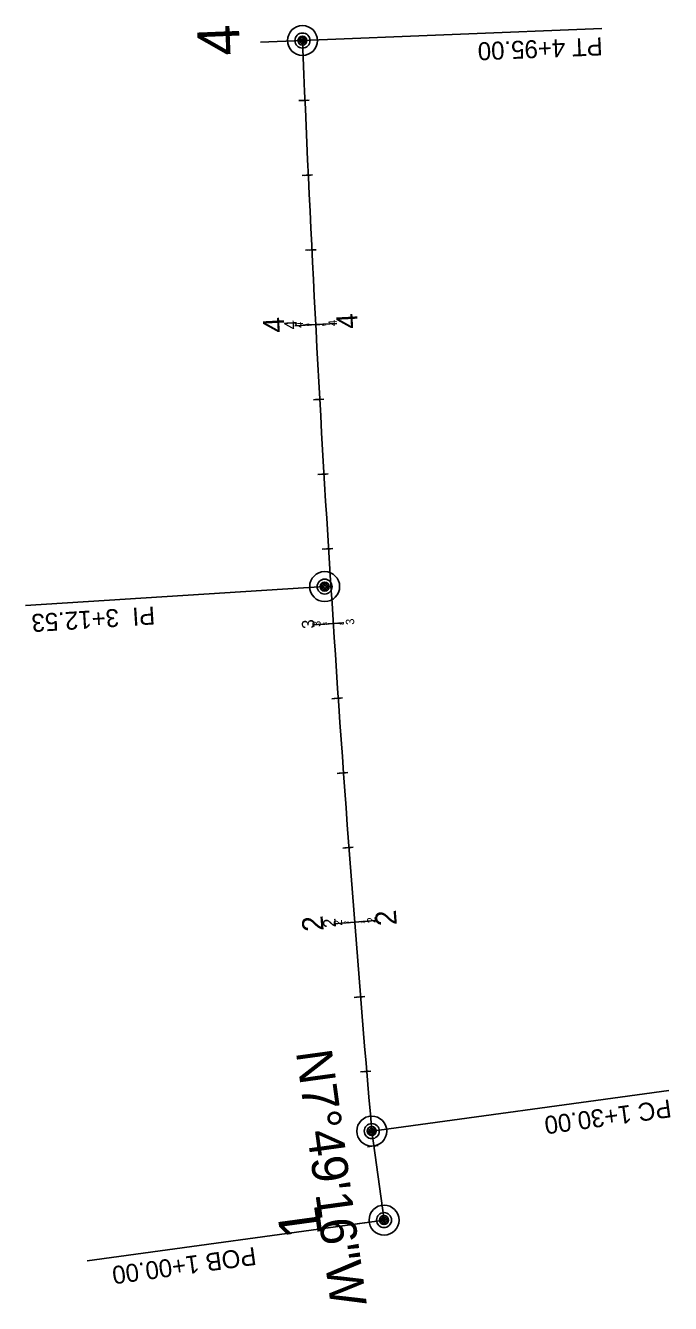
# Model space of a CAD drawing. Extents: x 594355 to 602437, y 155170 to 155921.
# Drawn here: x 594355.1 to 594570.2, y 155170.4 to 155597.2 of the extents above; entities that cross this region are included whole.
import ezdxf

# ---------------------------------------------------------------- set-up
doc = ezdxf.new("R2010")
doc.units = 0
for name, color, linetype in [('P_ALI_10', 7, 'Continuous'), ('P_ALI_100', 7, 'Continuous'), ('P_ALI_100_Equation', 7, 'Continuous'), ('P_ALI_100_Sta', 7, 'Continuous'), ('P_ALI_100_Tic', 7, 'Continuous'), ('P_ALI_100_TPI', 7, 'Continuous'), ('P_ALI_10_Flipped', 7, 'Continuous'), ('P_ALI_10_Sta', 7, 'Continuous'), ('P_ALI_10_Tic', 7, 'Continuous'), ('P_ALI_10_TPI', 7, 'Continuous'), ('P_ALI_20', 7, 'Continuous'), ('P_ALI_20_Flipped', 7, 'Continuous'), ('P_ALI_20_Sta', 7, 'Continuous'), ('P_ALI_20_Tic', 7, 'Continuous'), ('P_ALI_20_TPI', 7, 'Continuous'), ('P_ALI_30', 7, 'Continuous'), ('P_ALI_30_Sta', 7, 'Continuous'), ('P_ALI_30_Tic', 7, 'Continuous'), ('P_ALI_30_TPI', 7, 'Continuous'), ('P_ALI_50', 7, 'Continuous'), ('P_ALI_50_CPIData', 7, 'Continuous'), ('P_ALI_50_Flipped', 7, 'Continuous'), ('P_ALI_50_PIData', 7, 'Continuous'), ('P_ALI_50_Sta', 7, 'Continuous'), ('P_ALI_50_Tic', 7, 'Continuous'), ('P_ALI_50_TPI', 7, 'Continuous'), ('P_WAL', 7, 'Continuous')]:
    doc.layers.add(name, color=color, linetype=linetype)

msp = doc.modelspace()

# ---------------------------------------------------------------- linework, layer by layer
at = {"layer": 'P_ALI_10'}
msp.add_line((594474.66, 155198.21), (594470.58, 155227.93), dxfattribs=at)
msp.add_arc((602431.92, 155916.42), 7991.05, 182.325576, 184.942623, dxfattribs=at)
at = {"layer": 'P_ALI_100'}
msp.add_line((594474.66, 155198.21), (594470.58, 155227.93), dxfattribs=at)
msp.add_arc((602431.92, 155916.42), 7991.05, 182.325576, 184.942623, dxfattribs=at)
at = {"layer": 'P_ALI_100_Tic'}
for points in [[(594433.46, 155591.59), (594447.45, 155592.16)], [(594444.88, 155496.9), (594451.87, 155497.27)], [(594450.75, 155396.98), (594457.74, 155397.44)], [(594457.88, 155297.15), (594464.86, 155297.69)], [(594460.79, 155196.3), (594474.66, 155198.21)]]:
    msp.add_lwpolyline(points, dxfattribs=at)
at = {"layer": 'P_ALI_100_TPI'}
for centre in [(594447.45, 155592.16), (594454.85, 155409.78), (594470.58, 155227.93), (594474.66, 155198.21)]:
    msp.add_circle(centre, 5, dxfattribs=at)
at = {"layer": 'P_ALI_10_Flipped'}
for points in [[(594448.98, 155572.21), (594448.28, 155572.18)], [(594450.1, 155547.24), (594449.4, 155547.2)], [(594451.29, 155522.27), (594450.59, 155522.23)], [(594453.26, 155497.34), (594451.87, 155497.27)], [(594453.92, 155472.34), (594453.22, 155472.3)], [(594455.34, 155447.38), (594454.65, 155447.34)], [(594456.85, 155422.43), (594456.15, 155422.39)], [(594459.13, 155397.53), (594457.74, 155397.44)], [(594460.1, 155372.54), (594459.4, 155372.49)], [(594461.84, 155347.6), (594461.14, 155347.55)], [(594463.66, 155322.67), (594462.96, 155322.62)], [(594466.25, 155297.8), (594464.86, 155297.69)], [(594467.53, 155272.83), (594466.83, 155272.77)], [(594469.58, 155247.91), (594468.88, 155247.86)], [(594471.95, 155223.07), (594471.26, 155222.97)]]:
    msp.add_lwpolyline(points, dxfattribs=at)
at = {"layer": 'P_ALI_10_Tic'}
for points in [[(594447.58, 155572.15), (594448.28, 155572.18)], [(594448.7, 155547.17), (594449.4, 155547.2)], [(594449.89, 155522.2), (594450.59, 155522.23)], [(594450.47, 155497.19), (594451.87, 155497.27)], [(594452.52, 155472.26), (594453.22, 155472.3)], [(594453.95, 155447.3), (594454.65, 155447.34)], [(594455.45, 155422.35), (594456.15, 155422.39)], [(594456.34, 155397.35), (594457.74, 155397.44)], [(594458.7, 155372.45), (594459.4, 155372.49)], [(594460.44, 155347.5), (594461.14, 155347.55)], [(594462.26, 155322.57), (594462.96, 155322.62)], [(594463.46, 155297.58), (594464.86, 155297.69)], [(594466.13, 155272.71), (594466.83, 155272.77)], [(594468.18, 155247.8), (594468.88, 155247.86)], [(594470.57, 155222.88), (594471.26, 155222.97)]]:
    msp.add_lwpolyline(points, dxfattribs=at)
at = {"layer": 'P_ALI_10_TPI'}
for centre in [(594447.45, 155592.16), (594454.85, 155409.78), (594470.58, 155227.93), (594474.66, 155198.21)]:
    msp.add_circle(centre, 0.5, dxfattribs=at)
at = {"layer": 'P_ALI_20'}
msp.add_line((594474.66, 155198.21), (594470.58, 155227.93), dxfattribs=at)
msp.add_arc((602431.92, 155916.42), 7991.05, 182.325576, 184.942623, dxfattribs=at)
at = {"layer": 'P_ALI_20_Flipped'}
for points in [[(594449.68, 155572.24), (594448.28, 155572.18)], [(594450.8, 155547.27), (594449.4, 155547.2)], [(594451.99, 155522.3), (594450.59, 155522.23)], [(594454.66, 155497.41), (594451.87, 155497.27)], [(594454.61, 155472.38), (594453.22, 155472.3)], [(594456.04, 155447.43), (594454.65, 155447.34)], [(594457.55, 155422.47), (594456.15, 155422.39)], [(594460.53, 155397.62), (594457.74, 155397.44)], [(594460.8, 155372.59), (594459.4, 155372.49)], [(594462.54, 155347.65), (594461.14, 155347.55)], [(594464.35, 155322.72), (594462.96, 155322.62)], [(594467.65, 155297.91), (594464.86, 155297.69)], [(594468.23, 155272.88), (594466.83, 155272.77)], [(594470.28, 155247.97), (594468.88, 155247.86)], [(594472.65, 155223.16), (594471.26, 155222.97)]]:
    msp.add_lwpolyline(points, dxfattribs=at)
at = {"layer": 'P_ALI_20_Tic'}
for points in [[(594446.89, 155572.12), (594448.28, 155572.18)], [(594448, 155547.14), (594449.4, 155547.2)], [(594449.2, 155522.16), (594450.59, 155522.23)], [(594449.07, 155497.12), (594451.87, 155497.27)], [(594451.82, 155472.22), (594453.22, 155472.3)], [(594453.25, 155447.26), (594454.65, 155447.34)], [(594454.75, 155422.3), (594456.15, 155422.39)], [(594454.94, 155397.26), (594457.74, 155397.44)], [(594458, 155372.4), (594459.4, 155372.49)], [(594459.74, 155347.45), (594461.14, 155347.55)], [(594461.56, 155322.52), (594462.96, 155322.62)], [(594462.06, 155297.48), (594464.86, 155297.69)], [(594465.43, 155272.66), (594466.83, 155272.77)], [(594467.49, 155247.74), (594468.88, 155247.86)], [(594469.87, 155222.78), (594471.26, 155222.97)]]:
    msp.add_lwpolyline(points, dxfattribs=at)
at = {"layer": 'P_ALI_20_TPI'}
for centre in [(594447.45, 155592.16), (594454.85, 155409.78), (594470.58, 155227.93), (594474.66, 155198.21)]:
    msp.add_circle(centre, 1, dxfattribs=at)
at = {"layer": 'P_ALI_30'}
msp.add_line((594474.66, 155198.21), (594470.58, 155227.93), dxfattribs=at)
msp.add_arc((602431.92, 155916.42), 7991.05, 182.325576, 184.942623, dxfattribs=at)
at = {"layer": 'P_ALI_30_Tic'}
for points in [[(594446.19, 155572.09), (594448.28, 155572.18)], [(594447.3, 155547.11), (594449.4, 155547.2)], [(594448.5, 155522.13), (594450.59, 155522.23)], [(594447.67, 155497.05), (594451.87, 155497.27)], [(594451.12, 155472.19), (594453.22, 155472.3)], [(594452.55, 155447.22), (594454.65, 155447.34)], [(594454.06, 155422.26), (594456.15, 155422.39)], [(594453.55, 155397.17), (594457.74, 155397.44)], [(594457.3, 155372.35), (594459.4, 155372.49)], [(594459.05, 155347.41), (594461.14, 155347.55)], [(594460.86, 155322.46), (594462.96, 155322.62)], [(594460.67, 155297.37), (594464.86, 155297.69)], [(594464.74, 155272.6), (594466.83, 155272.77)], [(594466.79, 155247.68), (594468.88, 155247.86)], [(594469.18, 155222.69), (594471.26, 155222.97)]]:
    msp.add_lwpolyline(points, dxfattribs=at)
at = {"layer": 'P_ALI_30_TPI'}
for centre in [(594447.45, 155592.16), (594454.85, 155409.78), (594470.58, 155227.93), (594474.66, 155198.21)]:
    msp.add_circle(centre, 1.5, dxfattribs=at)
at = {"layer": 'P_ALI_50'}
msp.add_line((594474.66, 155198.21), (594470.58, 155227.93), dxfattribs=at)
msp.add_arc((602431.92, 155916.42), 7991.05, 182.325576, 184.942623, dxfattribs=at)
at = {"layer": 'P_ALI_50_CPIData'}
msp.add_lwpolyline([(594454.85, 155409.78), (594355.06, 155403.44)], dxfattribs=at)
msp.add_lwpolyline([(594454.85, 155409.78), (594355.06, 155403.44)], dxfattribs=at)
at = {"layer": 'P_ALI_50_Flipped'}
for points in [[(594458.86, 155497.63), (594451.87, 155497.27)], [(594461.23, 155397.67), (594457.74, 155397.44)], [(594471.83, 155298.23), (594464.86, 155297.69)]]:
    msp.add_lwpolyline(points, dxfattribs=at)
at = {"layer": 'P_ALI_50_PIData'}
for points in [[(594447.45, 155592.16), (594547.36, 155596.22)], [(594447.45, 155592.16), (594547.36, 155596.22)], [(594470.58, 155227.93), (594569.65, 155241.54)], [(594470.58, 155227.93), (594569.65, 155241.54)], [(594474.66, 155198.21), (594375.59, 155184.6)], [(594474.66, 155198.21), (594375.59, 155184.6)]]:
    msp.add_lwpolyline(points, dxfattribs=at)
at = {"layer": 'P_ALI_50_Tic'}
for points in [[(594444.88, 155496.9), (594451.87, 155497.27)], [(594454.24, 155397.21), (594457.74, 155397.44)], [(594457.88, 155297.15), (594464.86, 155297.69)]]:
    msp.add_lwpolyline(points, dxfattribs=at)
at = {"layer": 'P_ALI_50_TPI'}
for centre in [(594447.45, 155592.16), (594454.85, 155409.78), (594470.58, 155227.93), (594474.66, 155198.21)]:
    msp.add_circle(centre, 2.5, dxfattribs=at)
at = {"layer": 'P_WAL'}
msp.add_line((594474.66, 155198.21), (594470.58, 155227.93), dxfattribs=at)
msp.add_arc((602431.92, 155916.42), 7991.05, 182.325576, 184.942623, dxfattribs=at)

# ---------------------------------------------------------------- texts
msp.add_text('00', height=0.14, rotation=3.7237).set_placement((594457.75, 155397.3))
at = {"layer": 'P_ALI_100_Equation'}
msp.add_text('N7%%d49\'16"W', height=12, rotation=277.8211, dxfattribs=at).set_placement((594445.24, 155254.42))
at = {"layer": 'P_ALI_100_Sta'}
for s, rotation, p in [('4', 92.3256, (594426.63, 155587.34)), ('1', 97.8211, (594454.16, 155193.16))]:
    msp.add_text(s, height=14, rotation=rotation, dxfattribs=at).set_placement(p)
at = {"layer": 'P_ALI_10_Flipped'}
for s, rotation, p in [('4', 273.0067, (594453.94, 155497.77)), ('3', 273.7237, (594459.81, 155397.97)), ('2', 274.4407, (594466.92, 155298.25))]:
    msp.add_text(s, height=1.4, rotation=rotation, dxfattribs=at).set_placement(p)
at = {"layer": 'P_ALI_10_Sta'}
for s, rotation, p in [('4', 93.0067, (594449.79, 155496.76)), ('3', 93.7237, (594455.67, 155396.91)), ('2', 94.4407, (594462.79, 155297.13))]:
    msp.add_text(s, height=1.4, rotation=rotation, dxfattribs=at).set_placement(p)
at = {"layer": 'P_ALI_20_Flipped'}
for s, rotation, p in [('4', 93.0067, (594458.9, 155496.84)), ('3', 93.7237, (594464.77, 155397.1)), ('2', 94.4407, (594471.9, 155297.44))]:
    msp.add_text(s, height=2.8, rotation=rotation, dxfattribs=at).set_placement(p)
at = {"layer": 'P_ALI_20_Sta'}
for s, rotation, p in [('4', 93.0067, (594447.71, 155496.25)), ('3', 93.7237, (594453.6, 155396.37)), ('2', 94.4407, (594460.73, 155296.58))]:
    msp.add_text(s, height=2.8, rotation=rotation, dxfattribs=at).set_placement(p)
at = {"layer": 'P_ALI_30_Sta'}
for s, rotation, p in [('4', 93.0067, (594445.64, 155495.75)), ('3', 93.7237, (594451.53, 155395.84)), ('2', 94.4407, (594458.67, 155296.02))]:
    msp.add_text(s, height=4.2, rotation=rotation, dxfattribs=at).set_placement(p)
at = {"layer": 'P_ALI_50_CPIData'}
msp.add_text('PI  3+12.53', height=6, rotation=183.6341, dxfattribs=at).set_placement((594398.06, 155403.17))
msp.add_text('PI  3+12.53', height=6, rotation=183.6341, dxfattribs=at).set_placement((594398.06, 155403.17))
at = {"layer": 'P_ALI_50_Flipped'}
for s, rotation, p in [('4', 93.0067, (594465.95, 155496.02)), ('2', 94.4407, (594478.97, 155296.8))]:
    msp.add_text(s, height=7, rotation=rotation, dxfattribs=at).set_placement(p)
at = {"layer": 'P_ALI_50_PIData'}
for s, rotation, p in [('PT 4+95.00', 182.3256, (594547.49, 155593.22)), ('PT 4+95.00', 182.3256, (594547.49, 155593.22)), ('PC 1+30.00', 187.8211, (594570.06, 155238.56)), ('PC 1+30.00', 187.8211, (594570.06, 155238.56)), ('POB 1+00.00', 187.8211, (594431.56, 155189.26)), ('POB 1+00.00', 187.8211, (594431.56, 155189.26))]:
    msp.add_text(s, height=6, rotation=rotation, dxfattribs=at).set_placement(p)
at = {"layer": 'P_ALI_50_Sta'}
for s, rotation, p in [('4', 93.0067, (594441.48, 155494.73)), ('2', 94.4407, (594454.54, 155294.9))]:
    msp.add_text(s, height=7, rotation=rotation, dxfattribs=at).set_placement(p)

doc.saveas('drawing.dxf')
